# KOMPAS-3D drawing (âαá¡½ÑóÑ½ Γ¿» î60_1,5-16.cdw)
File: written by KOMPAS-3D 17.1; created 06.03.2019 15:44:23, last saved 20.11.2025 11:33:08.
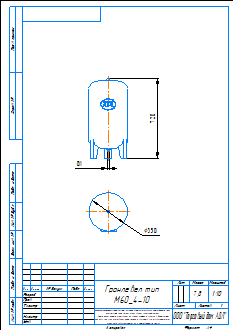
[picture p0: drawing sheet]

Sheet 1: A4, portrait

Title block, sheet 1: name: Гранлевел тип / М60_4-10; mass: 7,8; sheets: 1; sheet format: A4; stored path: C:\Users\kka\KOMPAS_Work\!Trash\ГРАНЛЕВЕЛ тип А Расширительный бак\KOMPAS 2D\Гранлевел тип А100_1,5-16.cdw

Views: Спереди 1, Спереди, Проекционный вид 2
Referenced files in C:\Users\mipv\Desktop\Тип А\SAT\: Гранлевел тип А60_4-10_1.a3d
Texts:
  kka
  adl
  Гранлевел тип А60_4-10
  Рама для чертежей
  Лит-Масса-Масштаб
  Материал-Предприятие
  Масштаб
  Изм.
  Лист
  № докум.
  Подп.
  Дата
  Лит.
  Разраб.
  Пров.
  Т.контр.
  Листов
  Внимание! Данный продукт является объектом авторского права ООО «Торговый Дом АДЛ».
  Запрещается изменение, копирование, распространение
  (в том числе путем копирования на другие сайты и ресурсы в Интернете)
  или любое иное использование информации и объектов без предварительного
  согласия правообладателя (ООО «Торговый Дом АДЛ»).
  Н.контр.
  Утв.
  ООО "Торговый дом АДЛ"
  Изменение
  Номер документа
  Подпись
  Обозначение документа
  Наименование изделия
  Масса изделия по ГОСТ 2.109-73
  Порядковый номер листа
  Общее количество листов в документе
  Характер работы, выполненной лицом, подписавшим документ
  Наименование или индекс предприятия, выпускающего документ
  Инв. № подл.
  Подп. и дата
  Взам. инв. №
  Инв. № дубл.
  Инвентарный номер подлинника по ГОСТ 2.501-68
  Подпись принявшего подлинник в отдел технической документации
  Инвентарный номер подлинника, взамен которого выпущен данный подлинник
  Инвентарный номер дубликата по ГОСТ 2.502-68
  Подпись принявшего дубликат в отдел технической документации
  Справ. №
  Перв. примен.
  Обозначение документа, взамен или на основании которого выпущен данный документ
  Обозначение документа, в котором впервые записан данный документ
  Подпись лица, копировавшего чертеж
  Обозначение формата листа
  !Рама для чертежа
Dimensions and other numbers on the sheet: 720; 350; 1:10; 1; 7,8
